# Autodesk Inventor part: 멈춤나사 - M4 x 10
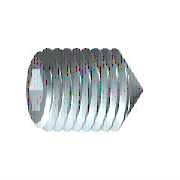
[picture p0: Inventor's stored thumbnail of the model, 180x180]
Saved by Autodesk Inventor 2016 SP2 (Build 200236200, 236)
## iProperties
Created: 2012-02
Part Number: 멈춤나사 - M4 x 10
Material: 강철, 연강
Description: 6각 소켓 머리 없는 멈춤 나사
Document SubType Name: Modeling
Standard: KS B 1028
Designer: mduedu
Standards Organization: KS
Language: ko-KR
Size Designation: 원추점 M4x10
Categories: <MemberInstance><Categories><Category DisplayName="조임쇠" InternalName="e4da775c-781d-43d5-af7c-5136215cf5a6" Mnemonic="FSTN"><Category DisplayName="볼트" InternalN
Density: 7.86 g/cm^3
Mass: 0.792069 g
Surface Area: 1.48192 cm^2
Volume: 0.100772 cm^3
Appearance: 강철
Author: mduedu
IsCustomPart: 1
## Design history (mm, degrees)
sketch "스케치1"
  geometry: L1 (0, 0)-(6.833, 0); L2 (10, 1.155)-(10, 2); L3 (10, 2)-(0, 2); L4 (10, 1.155)-(7.5, 1.155); L5 (7.5, 1.155)-(6.833, 0); L6 (0, -0.4)-(0, 2.4) reference; L7 (0, 2)-(0, 0)
  constraints: 13 end point, 3 parallel, 1 collinear, 1 perpendicular, 1 point on line
  dimensions: "d0" = 2.5 distance of L2.start L4.end (= INTI); "d1" = 60 deg angle of L5 L1; "d2" = 4 diameter of L3 L1 (= NND); "d3" = 2.3094 diameter of L4 L1 (= 1.1547 x SW); "d5" = 10 distance from line of L2 L3.end (= NLG)
revolve "본체" sketch "스케치1" stored, may be unused: angle "d6" = 90 deg
sketch "스케치2"
  geometry: L1 (-0.577, 1)-(0.577, 1); L2 (0.577, 1)-(1.155, 0); L3 (1.155, 0)-(0.577, -1); L4 (0.577, -1)-(-0.577, -1); L5 (-0.577, -1)-(-1.155, 0); L6 (-1.155, 0)-(-0.577, 1); 3 further points
  constraints: 12 end point, 1 coincident, 1 horizontal, 13 other
extrude "슬롯" join sketch "스케치2" taper "d7" = 0 deg; stored distance "d21" = 10
workaxis "Work Axis1"
workplane "Work Plane1"
sketch "스케치4"
  geometry: L1 (-5, 0.2)-(-3.2, 2) reference; L2 (-5, -0.2)-(-3.2, -2) reference; L3 (-3.2, 2)-(-5.2, 0); L4 (-3.2, -2)-(-5.2, 0); 2 further points
  constraints: 4 end point, 2 collinear, 1 coincident
body "Solid1"
feature "스레드" dims "d12" = 10 (= NLG), "d13" = 0
chamfer "모따기1" distance "d8" = 1.8 (computed from NND, SPD, FAWI); stored, may be unused: angle "d9" = 45 deg (= FAWI), second distance "d34" = 1.8 (computed from NND, SPD, FAWI)
chamfer "모따기2" distance "d10" = 0.42941 (= -0.5 x GD1 + 0.5 x NND); stored, may be unused: angle "d11" = 45 deg (= FAWI), second distance "d35" = 0.42941 (= -0.5 x GD1 + 0.5 x NND)
other parameters: "NND" = 4 [user parameter; used in 5 equation terms], "NLG" = 10 [user parameter; used in 2 equation terms], "INTI" = 2.5 [user parameter; used in 1 equation term], "FAWI" = 45 deg [user parameter; used in 4 equation terms], "SW" = 2 [user parameter; used in 2 equation terms], "GD1" = 3.14117 (= THREADDIA - 1.2269 x PTC) [user parameter; used in 2 equation terms], "d4" = 0, "FAWI1" = 45 deg [user parameter], "SPD" = 0.4 [user parameter; used in 2 equation terms], "d36" = 0, "d37" = 0, "GUL" = 0.42941 (= 0.61345 x PTC) [user parameter], "TPU" = 14.28571 (computed from PTC) [user parameter], "TOA" = 30 deg [user parameter], "THREADDIA" = 4 [user parameter; used in 1 equation term], "PTC" = 0.7 [user parameter; used in 4 equation terms], "GAL" = 0.42941 (= 0.61345 x PTC) [user parameter], "E0" = 2.31 (= 1.155 x SW) [user parameter]
